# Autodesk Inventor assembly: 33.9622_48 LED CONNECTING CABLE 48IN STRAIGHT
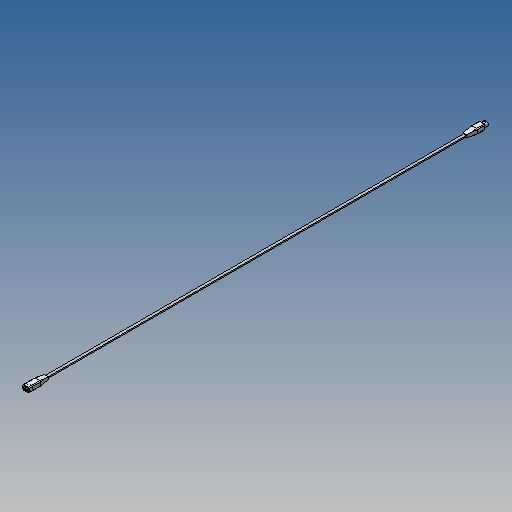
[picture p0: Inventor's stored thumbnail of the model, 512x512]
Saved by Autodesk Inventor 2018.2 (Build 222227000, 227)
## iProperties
Created: 2018-05
Part Number: 33.9622_48 LED CONNECTING CABLE 48IN STRAIGHT
Document SubType Name: Assembly
Designer: amoles
Author: amoles
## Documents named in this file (4)
- Y:\INVENTOR LIBRARIES\PARTS LIBRARY\WORKSTATION\LIGHTS OUTWATER PLASTICS\33.9622_48 LED CONNECTING CABLE 48IN STRAIGHT.iam
- Y:\INVENTOR LIBRARIES\PARTS LIBRARY\WORKSTATION\LIGHTS OUTWATER PLASTICS\SUBCOMPONENTS\33.9622 PLUG END FEMALE.ipt
- Y:\INVENTOR LIBRARIES\PARTS LIBRARY\WORKSTATION\LIGHTS OUTWATER PLASTICS\SUBCOMPONENTS\33.9622 PLUG END MALE.ipt
- Y:\INVENTOR LIBRARIES\PARTS LIBRARY\WORKSTATION\LIGHTS OUTWATER PLASTICS\SUBCOMPONENTS\33.9622_48 CORD STRAIGHT.ipt
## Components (3 placed, 3 different names)
1. 33.9622 PLUG END FEMALE:1 — Mate:1, Mate:2, Mate:3
2. 33.9622 PLUG END MALE:1 — Mate:4, Mate:5, Mate:6
3. 33.9622_48 CORD STRAIGHT:1 — Mate:1, Mate:2, Mate:3, Mate:4, Mate:5, Mate:6
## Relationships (6: Mate 6)
- Mate:1: 33.9622 PLUG END FEMALE:1 ↔ 33.9622_48 CORD STRAIGHT:1
- Mate:2: 33.9622 PLUG END FEMALE:1 ↔ 33.9622_48 CORD STRAIGHT:1
- Mate:3: 33.9622 PLUG END FEMALE:1 ↔ 33.9622_48 CORD STRAIGHT:1
- Mate:4: 33.9622 PLUG END MALE:1 ↔ 33.9622_48 CORD STRAIGHT:1
- Mate:5: 33.9622 PLUG END MALE:1 ↔ 33.9622_48 CORD STRAIGHT:1
- Mate:6: 33.9622 PLUG END MALE:1 ↔ 33.9622_48 CORD STRAIGHT:1
